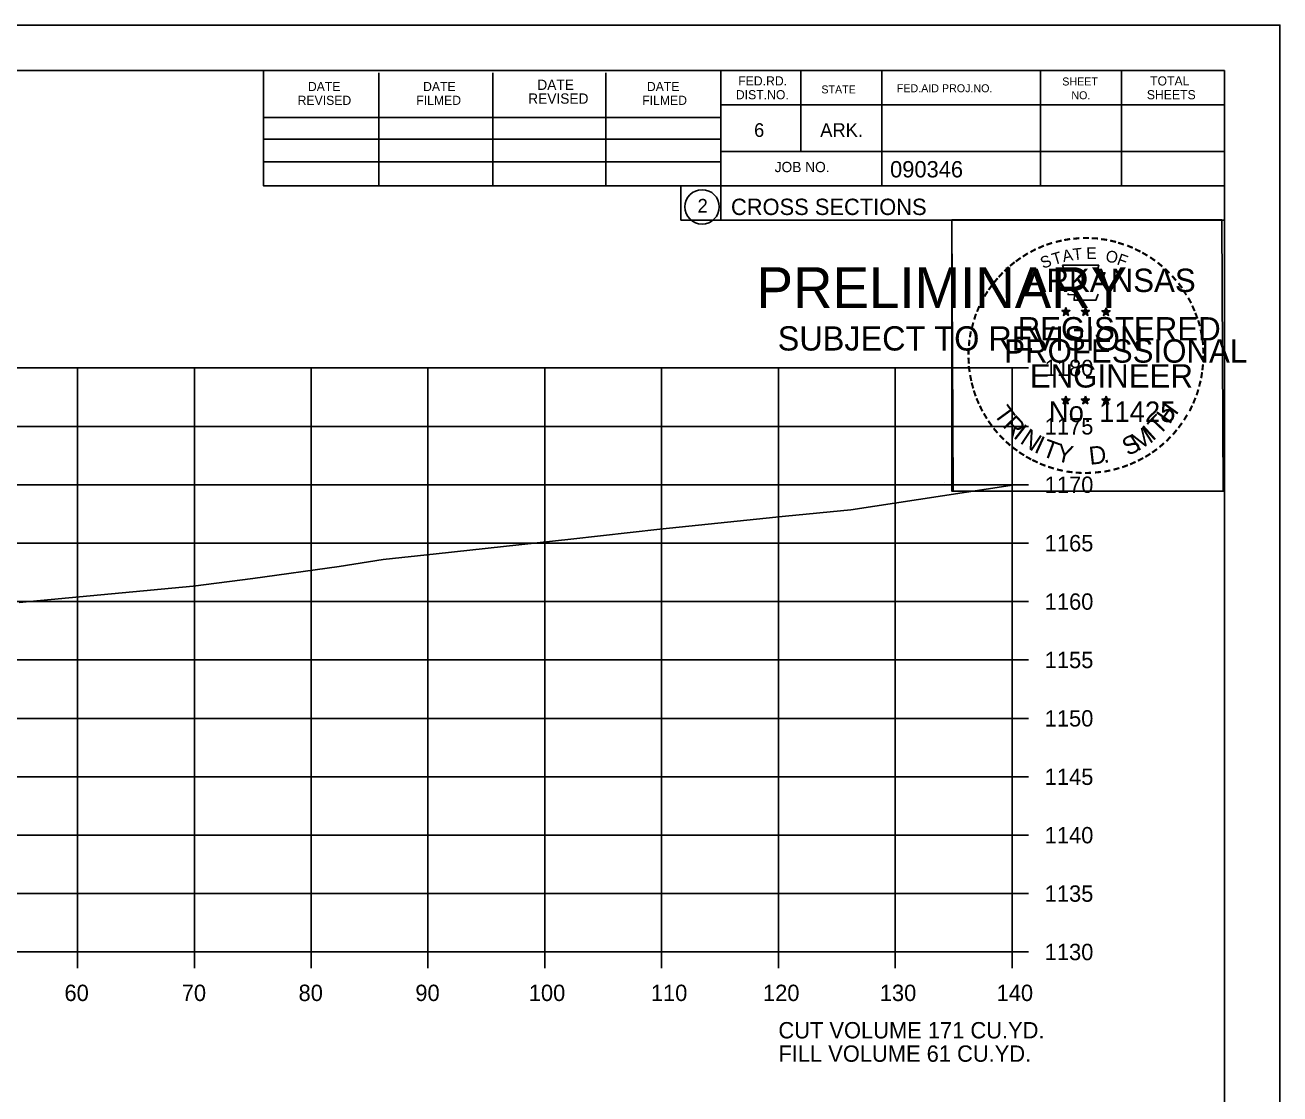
# Model space of a CAD drawing. Extents: x 1368971 to 1374497, y 378717 to 381839.
# Drawn here: x 1374389.8 to 1374497.3, y 380713.9 to 380805.4 of the extents above; entities that cross this region are included whole.
import ezdxf

# ---------------------------------------------------------------- set-up
doc = ezdxf.new("R2010")
doc.units = 0
for name, color, linetype in [('R_Axis', 7, 'Continuous'), ('R_Axis Annot', 7, 'Continuous'), ('R_Border', 7, 'Continuous'), ('R_Border PE', 7, 'Continuous'), ('R_Border Prem', 7, 'Continuous'), ('R_Exist Surface', 7, 'Continuous'), ('R_Grid', 7, 'Continuous'), ('R_No Plot', 7, 'Continuous')]:
    doc.layers.add(name, color=color, linetype=linetype)

msp = doc.modelspace()

# ---------------------------------------------------------------- linework, layer by layer
at = {"layer": 'R_Axis'}
for p, q in [((1374474.34, 380726.07), (1374474.34, 380776.07)), ((1374475.74, 380776.07), (1374474.34, 380776.07)), ((1374475.74, 380771.07), (1374474.34, 380771.07)), ((1374475.74, 380766.07), (1374474.34, 380766.07)), ((1374475.74, 380761.07), (1374474.34, 380761.07)), ((1374475.74, 380756.07), (1374474.34, 380756.07)), ((1374475.74, 380751.07), (1374474.34, 380751.07)), ((1374475.74, 380746.07), (1374474.34, 380746.07)), ((1374475.74, 380741.07), (1374474.34, 380741.07)), ((1374475.74, 380736.07), (1374474.34, 380736.07)), ((1374475.74, 380731.07), (1374474.34, 380731.07)), ((1374194.34, 380726.07), (1374474.34, 380726.07)), ((1374394.34, 380724.67), (1374394.34, 380726.07)), ((1374404.34, 380724.67), (1374404.34, 380726.07)), ((1374414.34, 380724.67), (1374414.34, 380726.07)), ((1374424.34, 380724.67), (1374424.34, 380726.07)), ((1374434.34, 380724.67), (1374434.34, 380726.07)), ((1374444.34, 380724.67), (1374444.34, 380726.07)), ((1374454.34, 380724.67), (1374454.34, 380726.07)), ((1374464.34, 380724.67), (1374464.34, 380726.07)), ((1374474.34, 380724.67), (1374474.34, 380726.07)), ((1374475.74, 380726.07), (1374474.34, 380726.07))]:
    msp.add_line(p, q, dxfattribs=at)
at = {"layer": 'R_Border'}
for p, q in [((1374176.34, 380801.53), (1374492.52, 380801.53)), ((1374410.26, 380791.65), (1374410.26, 380801.53)), ((1374420.12, 380791.65), (1374420.12, 380801.33)), ((1374429.88, 380791.65), (1374429.88, 380801.33)), ((1374439.56, 380791.65), (1374439.56, 380801.33)), ((1374449.42, 380801.53), (1374449.42, 380788.73)), ((1374456.26, 380801.53), (1374456.26, 380794.59)), ((1374463.2, 380801.53), (1374463.2, 380791.65)), ((1374476.78, 380801.53), (1374476.78, 380791.65)), ((1374483.72, 380801.53), (1374483.72, 380791.65)), ((1374492.52, 380596.07), (1374492.52, 380801.53)), ((1374492.52, 380798.59), (1374449.42, 380798.59)), ((1374492.52, 380798.61), (1374492.52, 380798.61)), ((1374410.26, 380797.51), (1374449.42, 380797.51)), ((1374410.26, 380795.65), (1374449.42, 380795.65)), ((1374492.52, 380794.59), (1374449.42, 380794.59)), ((1374452.38, 380794.59), (1374492.52, 380794.59)), ((1374410.26, 380791.65), (1374410.26, 380793.71)), ((1374410.26, 380793.71), (1374449.42, 380793.71)), ((1374492.52, 380791.65), (1374410.26, 380791.65)), ((1374449.42, 380788.73), (1374492.52, 380788.73))]:
    msp.add_line(p, q, dxfattribs=at)
msp.add_circle((1374447.81, 380789.86), 1.47, dxfattribs=at)
at = {"layer": 'R_Border PE'}
for p, q in [((1374478.61, 380780.98), (1374478.95, 380780.87)), ((1374478.61, 380780.98), (1374478.86, 380780.94)), ((1374478.61, 380780.98), (1374478.84, 380780.86)), ((1374478.74, 380780.57), (1374478.95, 380780.87)), ((1374478.74, 380780.57), (1374478.86, 380780.82)), ((1374478.74, 380780.57), (1374478.95, 380780.79)), ((1374478.95, 380781.23), (1374478.91, 380780.98)), ((1374478.95, 380780.87), (1374478.95, 380781.23)), ((1374478.95, 380781.23), (1374479, 380780.98)), ((1374479.3, 380780.98), (1374478.95, 380780.87)), ((1374479.17, 380780.57), (1374478.95, 380780.87)), ((1374479.17, 380780.57), (1374478.95, 380780.79)), ((1374479.3, 380780.98), (1374479.02, 380780.93)), ((1374479.17, 380780.57), (1374479.03, 380780.86)), ((1374479.3, 380780.98), (1374479.1, 380780.88)), ((1374480.28, 380780.98), (1374480.62, 380780.87)), ((1374480.28, 380780.98), (1374480.53, 380780.94)), ((1374480.28, 380780.98), (1374480.51, 380780.86)), ((1374480.41, 380780.57), (1374480.62, 380780.87)), ((1374480.41, 380780.57), (1374480.53, 380780.82)), ((1374480.41, 380780.57), (1374480.62, 380780.79)), ((1374480.62, 380781.23), (1374480.58, 380780.98)), ((1374480.62, 380780.87), (1374480.62, 380781.23)), ((1374480.62, 380781.23), (1374480.67, 380780.98)), ((1374480.97, 380780.98), (1374480.62, 380780.87)), ((1374480.84, 380780.57), (1374480.62, 380780.87)), ((1374480.84, 380780.57), (1374480.62, 380780.79)), ((1374480.97, 380780.98), (1374480.69, 380780.93)), ((1374480.84, 380780.57), (1374480.7, 380780.86)), ((1374480.97, 380780.98), (1374480.77, 380780.88)), ((1374482.04, 380780.97), (1374482.39, 380780.86)), ((1374482.04, 380780.97), (1374482.29, 380780.92)), ((1374482.04, 380780.97), (1374482.28, 380780.85)), ((1374482.17, 380780.56), (1374482.39, 380780.86)), ((1374482.17, 380780.56), (1374482.3, 380780.8)), ((1374482.17, 380780.56), (1374482.39, 380780.78)), ((1374482.39, 380781.22), (1374482.35, 380780.97)), ((1374482.39, 380780.86), (1374482.39, 380781.22)), ((1374482.39, 380781.22), (1374482.44, 380780.97)), ((1374482.74, 380780.97), (1374482.39, 380780.86)), ((1374482.6, 380780.56), (1374482.39, 380780.86)), ((1374482.6, 380780.56), (1374482.39, 380780.77)), ((1374482.74, 380780.97), (1374482.45, 380780.92)), ((1374482.6, 380780.56), (1374482.46, 380780.85)), ((1374482.74, 380780.97), (1374482.53, 380780.87)), ((1374478.6, 380773.41), (1374478.95, 380773.3)), ((1374478.6, 380773.41), (1374478.85, 380773.36)), ((1374478.6, 380773.41), (1374478.84, 380773.29)), ((1374478.73, 380773), (1374478.95, 380773.3)), ((1374478.73, 380773), (1374478.86, 380773.24)), ((1374478.73, 380773), (1374478.95, 380773.22)), ((1374478.95, 380773.66), (1374478.91, 380773.41)), ((1374478.95, 380773.3), (1374478.95, 380773.66)), ((1374478.95, 380773.66), (1374479, 380773.41)), ((1374479.3, 380773.41), (1374478.95, 380773.3)), ((1374479.16, 380773), (1374478.95, 380773.3)), ((1374479.16, 380773), (1374478.95, 380773.21)), ((1374479.3, 380773.41), (1374479.01, 380773.36)), ((1374479.16, 380773), (1374479.03, 380773.29)), ((1374479.3, 380773.41), (1374479.09, 380773.31)), ((1374480.27, 380773.41), (1374480.62, 380773.3)), ((1374480.27, 380773.41), (1374480.52, 380773.36)), ((1374480.27, 380773.41), (1374480.51, 380773.29)), ((1374480.4, 380773), (1374480.62, 380773.3)), ((1374480.4, 380773), (1374480.53, 380773.24)), ((1374480.4, 380773), (1374480.62, 380773.22)), ((1374480.62, 380773.66), (1374480.58, 380773.41)), ((1374480.62, 380773.3), (1374480.62, 380773.66)), ((1374480.62, 380773.66), (1374480.67, 380773.41)), ((1374480.97, 380773.41), (1374480.62, 380773.3)), ((1374480.83, 380773), (1374480.62, 380773.3)), ((1374480.83, 380773), (1374480.62, 380773.21)), ((1374480.97, 380773.41), (1374480.68, 380773.36)), ((1374480.83, 380773), (1374480.7, 380773.29)), ((1374480.97, 380773.41), (1374480.76, 380773.31)), ((1374482.04, 380773.4), (1374482.39, 380773.29)), ((1374482.04, 380773.4), (1374482.29, 380773.35)), ((1374482.04, 380773.4), (1374482.27, 380773.28)), ((1374482.17, 380772.99), (1374482.39, 380773.29)), ((1374482.17, 380772.99), (1374482.3, 380773.23)), ((1374482.17, 380772.99), (1374482.38, 380773.21)), ((1374482.39, 380773.65), (1374482.35, 380773.4)), ((1374482.6, 380772.99), (1374482.38, 380773.2)), ((1374482.39, 380773.29), (1374482.39, 380773.65)), ((1374482.39, 380773.65), (1374482.44, 380773.4)), ((1374482.73, 380773.4), (1374482.39, 380773.29)), ((1374482.6, 380772.99), (1374482.39, 380773.29)), ((1374482.73, 380773.4), (1374482.45, 380773.35)), ((1374482.6, 380772.99), (1374482.46, 380773.28)), ((1374482.73, 380773.4), (1374482.53, 380773.3))]:
    msp.add_line(p, q, dxfattribs=at)
for points in [[(1374478.65, 380784.86), (1374478.92, 380784.03)], [(1374482.16, 380783.94), (1374482.3, 380784.22), (1374481.61, 380784.2), (1374481.76, 380784.86), (1374478.65, 380784.86)], [(1374479.14, 380782.44), (1374479.14, 380782.35), (1374479.7, 380782.33), (1374479.65, 380781.86), (1374481.52, 380781.86), (1374481.72, 380782.39)], [(1374478.95, 380781.23), (1374479.17, 380780.57), (1374478.61, 380780.98), (1374479.3, 380780.98), (1374478.74, 380780.57), (1374478.95, 380781.23)], [(1374480.62, 380781.23), (1374480.84, 380780.57), (1374480.28, 380780.98), (1374480.97, 380780.98), (1374480.41, 380780.57), (1374480.62, 380781.23)], [(1374482.39, 380781.22), (1374482.6, 380780.56), (1374482.04, 380780.97), (1374482.74, 380780.97), (1374482.17, 380780.56), (1374482.39, 380781.22)], [(1374478.95, 380773.66), (1374479.16, 380773), (1374478.6, 380773.41), (1374479.3, 380773.41), (1374478.73, 380773), (1374478.95, 380773.66)], [(1374480.62, 380773.66), (1374480.83, 380773), (1374480.27, 380773.41), (1374480.97, 380773.41), (1374480.4, 380773), (1374480.62, 380773.66)], [(1374482.39, 380773.65), (1374482.6, 380772.99), (1374482.04, 380773.4), (1374482.73, 380773.4), (1374482.17, 380772.99), (1374482.39, 380773.65)]]:
    msp.add_lwpolyline(points, dxfattribs=at)
for centre, radius in [((1374478.95, 380780.87), 0.172), ((1374478.95, 380780.87), 0.145), ((1374478.95, 380780.87), 0.116), ((1374478.95, 380780.87), 0.0991), ((1374478.95, 380780.87), 0.0747), ((1374478.95, 380780.87), 0.0495), ((1374478.95, 380780.87), 0.0296), ((1374480.62, 380780.87), 0.172), ((1374480.62, 380780.87), 0.145), ((1374480.62, 380780.87), 0.116), ((1374480.62, 380780.87), 0.0991), ((1374480.62, 380780.87), 0.0747), ((1374480.62, 380780.87), 0.0495), ((1374480.62, 380780.87), 0.0296), ((1374482.39, 380780.86), 0.172), ((1374482.39, 380780.86), 0.145), ((1374482.39, 380780.86), 0.116), ((1374482.39, 380780.86), 0.0991), ((1374482.39, 380780.86), 0.0747), ((1374482.39, 380780.86), 0.0495), ((1374482.39, 380780.86), 0.0296), ((1374478.95, 380773.3), 0.172), ((1374478.95, 380773.3), 0.145), ((1374478.95, 380773.3), 0.116), ((1374478.95, 380773.3), 0.0991), ((1374478.95, 380773.3), 0.0747), ((1374478.95, 380773.3), 0.0495), ((1374478.95, 380773.3), 0.0296), ((1374480.62, 380773.3), 0.172), ((1374480.62, 380773.3), 0.145), ((1374480.62, 380773.3), 0.116), ((1374480.62, 380773.3), 0.0991), ((1374480.62, 380773.3), 0.0747), ((1374480.62, 380773.3), 0.0495), ((1374480.62, 380773.3), 0.0296), ((1374482.39, 380773.29), 0.172), ((1374482.39, 380773.29), 0.145), ((1374482.39, 380773.29), 0.116), ((1374482.39, 380773.29), 0.0991), ((1374482.39, 380773.29), 0.0747), ((1374482.39, 380773.29), 0.0495), ((1374482.39, 380773.29), 0.0296)]:
    msp.add_circle(centre, radius, dxfattribs=at)
at = {"layer": 'R_Exist Surface'}
msp.add_lwpolyline([(1374389.35, 380755.99), (1374404.24, 380757.4), (1374409.35, 380758.03), (1374416.75, 380759.08), (1374420.5, 380759.66), (1374425.05, 380760.15), (1374436.57, 380761.41), (1374444.2, 380762.26), (1374454.96, 380763.39), (1374460.55, 380763.93), (1374474.17, 380766), (1374474.34, 380766.02)], dxfattribs=at)
at = {"layer": 'R_Grid'}
for p, q in [((1374194.34, 380776.07), (1374474.34, 380776.07)), ((1374394.34, 380726.07), (1374394.34, 380776.07)), ((1374404.34, 380726.07), (1374404.34, 380776.07)), ((1374414.34, 380726.07), (1374414.34, 380776.07)), ((1374424.34, 380726.07), (1374424.34, 380776.07)), ((1374434.34, 380726.07), (1374434.34, 380776.07)), ((1374444.34, 380726.07), (1374444.34, 380776.07)), ((1374454.34, 380726.07), (1374454.34, 380776.07)), ((1374464.34, 380726.07), (1374464.34, 380776.07)), ((1374474.34, 380726.07), (1374474.34, 380776.07)), ((1374194.34, 380771.07), (1374474.34, 380771.07)), ((1374194.34, 380766.07), (1374474.34, 380766.07)), ((1374194.34, 380761.07), (1374474.34, 380761.07)), ((1374194.34, 380756.07), (1374474.34, 380756.07)), ((1374194.34, 380751.07), (1374474.34, 380751.07)), ((1374194.34, 380746.07), (1374474.34, 380746.07)), ((1374194.34, 380741.07), (1374474.34, 380741.07)), ((1374194.34, 380736.07), (1374474.34, 380736.07)), ((1374194.34, 380731.07), (1374474.34, 380731.07)), ((1374194.34, 380726.07), (1374474.34, 380726.07))]:
    msp.add_line(p, q, dxfattribs=at)
at = {"layer": 'R_No Plot'}
for p, q in [((1374163.94, 380805.42), (1374497.27, 380805.42)), ((1374468.56, 380766.27), (1374468.56, 380766.27))]:
    msp.add_line(p, q, dxfattribs=at)
for points in [[(1374163.93, 380805.42), (1374497.27, 380805.42), (1374497.27, 380592.08), (1374163.93, 380592.08)], [(1374410.26, 380801.53), (1374410.26, 380791.65), (1374445.99, 380791.65), (1374445.99, 380788.73), (1374469.19, 380788.73), (1374469.19, 380765.51), (1374492.52, 380765.51), (1374492.52, 380596.07), (1374176.34, 380596.07), (1374176.34, 380801.53)], [(1374469.19, 380788.76), (1374492.29, 380788.76), (1374492.41, 380765.51), (1374469.31, 380765.51)]]:
    msp.add_lwpolyline(points, close=True, dxfattribs=at)

# ---------------------------------------------------------------- texts
at = {"layer": 'R_Axis Annot'}
for s, p in [('1180', (1374477.14, 380775.37)), ('1175', (1374477.14, 380770.37)), ('1170', (1374477.14, 380765.37)), ('1165', (1374477.14, 380760.37)), ('1160', (1374477.14, 380755.37)), ('1155', (1374477.14, 380750.37)), ('1150', (1374477.14, 380745.37)), ('1145', (1374477.14, 380740.37)), ('1140', (1374477.14, 380735.37)), ('1135', (1374477.14, 380730.37)), ('1130', (1374477.14, 380725.37)), ('60', (1374393.22, 380721.87)), ('70', (1374403.26, 380721.87)), ('80', (1374413.26, 380721.87)), ('90', (1374423.26, 380721.87)), ('100', (1374432.97, 380721.87)), ('110', (1374443.42, 380721.87)), ('120', (1374453.02, 380721.87)), ('130', (1374463.02, 380721.87)), ('140', (1374473.02, 380721.87)), ('CUT VOLUME 171 CU.YD.', (1374454.34, 380718.67)), ('FILL VOLUME 61 CU.YD.', (1374454.34, 380716.67))]:
    msp.add_text(s, height=1.4, dxfattribs=at).set_placement(p)
at = {"layer": 'R_Border'}
for s, height, p in [('FED.RD.', 0.782, (1374450.9, 380800.25)), ('TOTAL', 0.782, (1374486.16, 380800.25)), ('DATE', 0.782, (1374414.06, 380799.77)), ('DATE', 0.782, (1374423.92, 380799.77)), ('DATE', 0.879, (1374433.7, 380799.87)), ('DATE', 0.782, (1374443.08, 380799.77)), ('STATE', 0.684, (1374458.02, 380799.57)), ('FED.AID PROJ.NO.', 0.684, (1374464.48, 380799.67)), ('SHEET', 0.684, (1374478.64, 380800.25)), ('REVISED', 0.782, (1374413.18, 380798.59)), ('FILMED', 0.782, (1374423.34, 380798.59)), ('REVISED', 0.879, (1374432.92, 380798.69)), ('FILMED', 0.782, (1374442.68, 380798.59)), ('DIST.NO.', 0.782, (1374450.7, 380799.07)), ('NO.', 0.684, (1374479.42, 380799.07)), ('SHEETS', 0.782, (1374485.88, 380799.07)), ('6', 1.17, (1374452.26, 380795.85)), ('ARK.', 1.172, (1374457.92, 380795.85)), ('JOB NO.', 0.879, (1374454.02, 380792.83)), ('2', 1.17, (1374447.42, 380789.37)), ('CROSS SECTIONS', 1.4, (1374450.28, 380789.16))]:
    msp.add_text(s, height=height, dxfattribs=at).set_placement(p)
msp.add_text('090346', height=1.4, rotation=360, dxfattribs=at).set_placement((1374463.9, 380792.38))
at = {"layer": 'R_Border PE'}
for s, height, rotation, p in [('-', 1.6, 13.6301, (1374478.14, 380786.23)), ('-', 1.6, 10.2193, (1374478.82, 380786.39)), ('-', 1.6, 5.8968, (1374479.55, 380786.5)), ('-', 1.6, 0.1862, (1374480.32, 380786.57)), ('-', 1.6, 357.743, (1374481.05, 380786.56)), ('-', 1.6, 352.1617, (1374481.79, 380786.5)), ('-', 1.6, 347.2049, (1374482.51, 380786.39)), ('-', 1.6, 34.0636, (1374475.53, 380785.03)), ('-', 1.6, 28.7918, (1374476.13, 380785.4)), ('-', 1.6, 24.3072, (1374476.76, 380785.72)), ('-', 1.6, 19.1761, (1374477.39, 380785.99)), ('T', 1, 16.4036, (1374477.92, 380784.87)), ('A', 1, 11.2132, (1374478.74, 380785.12)), ('T', 1, 6.0228, (1374479.59, 380785.28)), ('E', 1, 0.8323, (1374480.7, 380785.39)), ('O', 1, 350.4515, (1374482.3, 380785.18)), ('-', 1.6, 342.3362, (1374483.14, 380786.23)), ('-', 1.6, 337.8551, (1374483.88, 380786.01)), ('-', 1.6, 334.1211, (1374484.51, 380785.74)), ('-', 1.6, 329.6409, (1374485.09, 380785.46)), ('-', 1.6, 38.9507, (1374474.48, 380784.26)), ('-', 1.6, 36.2317, (1374474.95, 380784.63)), ('S', 1, 21.594, (1374477, 380784.54)), ('F', 1, 340.0707, (1374483.25, 380784.96)), ('-', 1.6, 325.8627, (1374485.73, 380785.09)), ('-', 1.6, 320.5297, (1374486.34, 380784.67)), ('-', 1.6, 50.6142, (1374473.19, 380782.88)), ('-', 1.6, 48.423, (1374473.6, 380783.36)), ('-', 1.6, 42.9622, (1374474.04, 380783.84)), ('-', 1.6, 315.5786, (1374486.94, 380784.18)), ('-', 1.6, 309.8797, (1374487.51, 380783.63)), ('-', 1.6, 54.2325, (1374472.78, 380782.31)), ('-', 1.6, 306.6522, (1374488.04, 380783.03)), ('-', 1.4, 303.6753, (1374488.52, 380782.46)), ('-', 1.6, 62.8713, (1374472.14, 380781.17)), ('-', 1.6, 58.0706, (1374472.45, 380781.78)), ('-', 1.6, 299.6684, (1374488.84, 380781.85)), ('-', 1.6, 72.3945, (1374471.66, 380779.93)), ('-', 1.6, 67.7743, (1374471.88, 380780.56)), ('-', 1.6, 294.6628, (1374489.16, 380781.24)), ('-', 1.6, 290.5728, (1374489.42, 380780.66)), ('-', 1.6, 75.461, (1374471.47, 380779.21)), ('-', 1.6, 285.1233, (1374489.66, 380780.08)), ('-', 1.6, 85.1863, (1374471.26, 380777.81)), ('-', 1.6, 81.2013, (1374471.33, 380778.5)), ('-', 1.6, 280.5493, (1374489.86, 380779.34)), ('-', 1.6, 276.5962, (1374490.02, 380778.57)), ('-', 1.6, 89.0622, (1374471.23, 380777.11)), ('-', 1.6, 274.3301, (1374490.08, 380777.85)), ('-', 1.6, 94.1959, (1374471.27, 380776.38)), ('-', 1.6, 263.5172, (1374490.09, 380776.55)), ('-', 1.6, 269.9407, (1374490.11, 380777.22)), ('-', 1.6, 98.9479, (1374471.34, 380775.72)), ('-', 1.6, 101.7149, (1374471.48, 380774.98)), ('-', 1.6, 260.9953, (1374490.02, 380775.9)), ('-', 1.6, 105.4578, (1374471.64, 380774.39)), ('-', 1.6, 109.0874, (1374471.85, 380773.76)), ('-', 1.6, 252.8681, (1374489.73, 380774.5)), ('-', 1.6, 255.7626, (1374489.91, 380775.22)), ('-', 1.6, 114.0643, (1374472.11, 380773.16)), ('H', 1.54, 54.6088, (1374487.83, 380771.17)), ('-', 1.6, 247.8887, (1374489.51, 380773.83)), ('-', 1.6, 115.7288, (1374472.41, 380772.54)), ('-', 1.6, 120.4471, (1374472.77, 380771.96)), ('T', 1.54, 306.0406, (1374472.71, 380772.13)), ('R', 1.54, 314.005, (1374473.47, 380771.09)), ('T', 1.54, 46.6444, (1374486.94, 380770.23)), ('-', 1.6, 239.0712, (1374488.85, 380772.45)), ('-', 1.6, 244.6197, (1374489.25, 380773.2)), ('-', 1.6, 125.8934, (1374473.17, 380771.4)), ('-', 1.6, 130.7181, (1374473.63, 380770.84)), ('I', 1.54, 321.9694, (1374474.37, 380770.15)), ('M', 1.54, 32.6563, (1374485.1, 380768.9)), ('I', 1.54, 42.1136, (1374486.38, 380769.75)), ('-', 1.6, 233.8452, (1374488.45, 380771.8)), ('-', 1.6, 134.2238, (1374474.15, 380770.3)), ('-', 1.6, 138.9338, (1374474.68, 380769.83)), ('N', 1.54, 326.5002, (1374474.94, 380769.68)), ('I', 1.54, 335.3603, (1374476.15, 380768.9)), ('T', 1.54, 339.8912, (1374476.81, 380768.57)), ('S', 1.54, 26.9312, (1374484.26, 380768.5)), ('-', 1.6, 225.7653, (1374487.54, 380770.67)), ('-', 1.6, 231.2538, (1374488.02, 380771.23)), ('-', 1.6, 144.6463, (1374475.23, 380769.43)), ('-', 1.6, 148.0898, (1374475.79, 380769.06)), ('Y', 1.54, 347.8556, (1374478.03, 380768.12)), ('D', 1.54, 6.3969, (1374481.01, 380767.77)), ('-', 1.6, 212.2491, (1374485.94, 380769.3)), ('-', 1.6, 215.7363, (1374486.47, 380769.68)), ('-', 1.6, 221.0851, (1374487.02, 380770.16)), ('-', 1.6, 151.5704, (1374476.37, 380768.73)), ('-', 1.6, 154.6002, (1374476.89, 380768.49)), ('-', 1.6, 158.5612, (1374477.52, 380768.23)), ('-', 1.6, 162.7983, (1374478.2, 380768.02)), ('.', 1.54, 13.7642, (1374482.2, 380767.89)), ('-', 1.6, 200.7184, (1374484.13, 380768.36)), ('-', 1.6, 204.2516, (1374484.75, 380768.63)), ('-', 1.6, 207.3568, (1374485.38, 380768.95)), ('-', 1.6, 167.5555, (1374478.92, 380767.85)), ('-', 1.6, 173.1155, (1374479.69, 380767.74)), ('-', 1.6, 176.5183, (1374480.44, 380767.69)), ('-', 1.6, 181.5918, (1374481.18, 380767.71)), ('-', 1.6, 185.8167, (1374481.99, 380767.79)), ('-', 1.6, 191.2858, (1374482.73, 380767.92)), ('-', 1.6, 195.4743, (1374483.46, 380768.12))]:
    msp.add_text(s, height=height, rotation=rotation, dxfattribs=at).set_placement(p)
for s, height, p in [('ARKANSAS', 2, (1374475.5, 380782.57)), ('DWB', 0.01, (1374478.94, 380780.86)), ('DWB', 0.01, (1374480.61, 380780.86)), ('DWB', 0.01, (1374482.38, 380780.85)), ('REGISTERED', 2, (1374474.82, 380778.42)), ('PROFESSIONAL', 2, (1374473.67, 380776.52)), ('ENGINEER', 2, (1374475.86, 380774.39)), ('No. 11425', 1.757, (1374477.49, 380771.44)), ('DWB', 0.01, (1374478.94, 380773.29)), ('DWB', 0.01, (1374480.61, 380773.29)), ('DWB', 0.01, (1374482.37, 380773.28))]:
    msp.add_text(s, height=height, dxfattribs=at).set_placement(p)
at = {"layer": 'R_Border Prem'}
for s, height, p in [('PRELIMINARY', 3.5, (1374452.47, 380781.19)), ('DWB', 0.01, (1374453.22, 380783.04)), ('SUBJECT TO REVISION', 2.0751, (1374454.28, 380777.56))]:
    msp.add_text(s, height=height, dxfattribs=at).set_placement(p)

doc.saveas('drawing.dxf')
